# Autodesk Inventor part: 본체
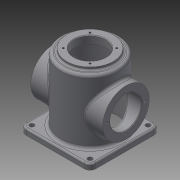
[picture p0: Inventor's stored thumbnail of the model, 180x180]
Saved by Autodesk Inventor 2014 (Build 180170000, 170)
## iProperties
Created: 2015-10
Part Number: 본체
Material: Generic
Document SubType Name: Modeling
Designer: 시험용
Density: 1 g/cm^3
Appearance: Default
Author: 시험용
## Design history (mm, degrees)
sketch "스케치1"
  geometry: L1 (0, 0)-(-125, 0); L2 (-125, 27)-(-125, 40); L3 (-125, 40)-(-120, 40); L4 (-120, 40)-(-120, 50); L5 (-120, 50)-(0, 50); L6 (0, 50)-(0, 45); L7 (0, 45)-(-112, 45); L8 (-112, 45)-(-112, 27); L9 (-112, 27)-(-125, 27)
  constraints: 18 end point, 6 parallel, 2 perpendicular, 2 vertical alignment, 1 horizontal
  dimensions: "d0" = 125 distance between parallel lines of L2 L6; "d2" = 120 distance between parallel lines of L6 L4; "d3" = 112 distance from line of L6.end L8; "d4" = 54 diameter of L9 L1; "d5" = 90 diameter of L7 L1; "d6" = 100 diameter of L5 L1; "d7" = 80 diameter of L3 L1
revolve "회전1" sketch "스케치1" stored, may be unused: angle "d8" = 90 deg
sketch "스케치3"
  geometry: C1 r 40 at (-60, 0); C2 r 27 at (-60, 0); 1 further point
  constraints: 2 centre point, 1 horizontal alignment
  dimensions: "d25" = 80 diameter of C1; "d26" = 60 distance of point (0, 0) C1.centre; "d27" = 54 diameter of C2
extrude "돌출1" join sketch "스케치3" stored distance "d28" = 124; taper "d29" = 0 deg
hole "구멍2" diameter "d32" = 54; stored, may be unused: countersink angle "d36" = 90 deg, drill point angle "d38" = 118 deg; dims "d30" = 10, "d31" = 10, "d33" = 6, "d34" = 4, "d35" = 2, "d37" = 8
hole "구멍3" diameter "d41" = 90; stored, may be unused: countersink angle "d45" = 90 deg, drill point angle "d47" = 0 deg; dims "d42" = 6, "d43" = 4, "d44" = 2, "d46" = 110, "d50" = 10, "d51" = 10
chamfer "모따기1" distance "d48" = 1; stored, may be unused: second distance "d49" = 2, angle "d52" = 45 deg
sketch "스케치4"
  geometry: L1 (-50, -60)-(50, -60); L2 (60, -50)-(60, 50); L3 (50, 60)-(-50, 60); L4 (-60, 50)-(-60, -50); L5 (-60, -60)-(60, 60); L6 (60, -60)-(-60, 60); C1 r 50 at (0, 0) reference; C2 r 4 at (-50, 50); C3 r 4 at (50, 50); C4 r 4 at (50, -50); C5 r 4 at (-50, -50); C6 r 50 at (0, 0); A1 r 10 centre (-50, 50) between (-50, 60) and (-60, 50); A2 r 10 centre (-50, -50) between (-60, -50) and (-50, -60); A3 r 10 centre (50, -50) between (50, -60) and (60, -50); A4 r 10 centre (50, 50) between (60, 50) and (50, 60)
  constraints: 12 end point, 9 centre point, 8 point on circle, 8 point on line, 8 tangent, 7 equal radius, 5 coincident, 2 midpoint, 2 parallel, 1 horizontal, 1 perpendicular
  dimensions: "d54" = 120 distance of L5.end L6.end; "d55" = 120 distance of L6.end L5.start; "d56" = 10 radius of A1; "d57" = 8 diameter of C2
extrude "돌출2" join sketch "스케치4" distance "d58" = 10; taper "d59" = 0 deg
fillet "모깎기3" dims "d60" = 5
fillet "모깎기4" dims "d61" = 3
fillet "모깎기5" dims "d62" = 3
chamfer "모따기2" distance "d63" = 3; stored, may be unused: second distance "d64" = 2, angle "d65" = 45 deg
sketch "스케치5" dims "d67" = 65
  geometry: L1 (0, 40)-(0, 0); L2 (0, 0)-(28.284, 28.284); C1 r 28 at (0, 0) reference; A1 r 40 centre (0, 0) between (0, 40) and (28.284, 28.284) reference; 1 further point
  constraints: 4 end point, 2 point on circle, 1 point on line, 1 vertical, 3 other
  dimensions: "d66" = 45 deg angle of L1 L2
hole "구멍4" sketch "스케치5" at (22.981, 22.981) diameter "d68" = 3.242; stored, may be unused: countersink angle "d72" = 90 deg, drill point angle "d74" = 118 deg; dims "d69" = 8, "d70" = 4, "d71" = 2, "d73" = 10
sketch "스케치6" dims "d78" = 65
  geometry: C1 r 40 at (0, 0) reference; 2 further points
  constraints: 2 vertical alignment, 2 other
hole "구멍5" sketch "스케치6" at (0, 32.5) diameter "d79" = 3.242; stored, may be unused: countersink angle "d83" = 90 deg, drill point angle "d85" = 118 deg; dims "d80" = 8, "d81" = 4, "d82" = 2, "d84" = 10
sketch "스케치7" dims "d0" = 125, "d2" = 120, "d3" = 112, "d4" = 54, "d5" = 90, "d6" = 100, "d7" = 80, "d54" = 120, "d55" = 120, "d56" = 10, "d57" = 8
  geometry: L1 (0, 0)-(0, 100) reference; L2 (46.136, 53.377)-(93.864, 53.377); L3 (93.864, 53.377)-(93.864, 46.623); L4 (93.864, 46.623)-(46.136, 46.623); L5 (46.136, 46.623)-(46.136, 53.377); L6 (46.136, 53.377)-(93.864, 46.623); 4 further points
  constraints: 3 midpoint, 2 end point, 1 horizontal alignment, 1 vertical alignment, 2 other
  dimensions: "d89" = 70 distance of point (0, 50) point (70, 50); "d90" = 47.72772 distance of L2.start L2.end; "d91" = 6.75365 distance of L2.end L3.end
feature "엠보싱1" sketch "스케치7" dims "d0" = 125, "d2" = 120, "d3" = 112, "d4" = 54, "d5" = 90, "d6" = 100, "d7" = 80, "d42" = 6, "d92" = 0.5, "d93" = 0
fillet "모깎기6" dims "d94" = 3
fillet "모깎기7" dims "d95" = 3
node "솔리드1"
pattern_circular "원형 패턴1" dims angle "d76" = 360 deg
mirror "대칭1"
pattern_circular "원형 패턴2" dims angle "d87" = 360 deg
